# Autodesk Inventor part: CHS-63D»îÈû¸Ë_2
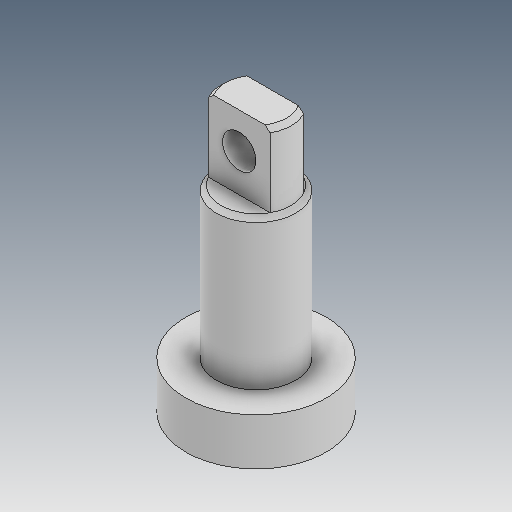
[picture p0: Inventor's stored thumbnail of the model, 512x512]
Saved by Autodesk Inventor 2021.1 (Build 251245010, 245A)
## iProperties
Created: 2019-05
Part Number: CHS-63D»îÈû¸Ë_2
Material: Ogólny
Document SubType Name: Modeling
Designer: user
Density: 1 g/cm^3
Appearance: Domyślna
Author: user
Revision Number: ÈÎºÎ
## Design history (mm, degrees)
feature "ÊäÈë1"
feature "ÊäÈë2"
node "Bryła1"
node "Bryła2"
